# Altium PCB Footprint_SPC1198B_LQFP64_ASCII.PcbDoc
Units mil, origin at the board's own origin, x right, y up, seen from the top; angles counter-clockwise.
Board outline 6000 x 4000 mil, 2 copper layers (Top Layer, Bottom Layer); 1 components, 0 nets, 64 pads, 0 vias.
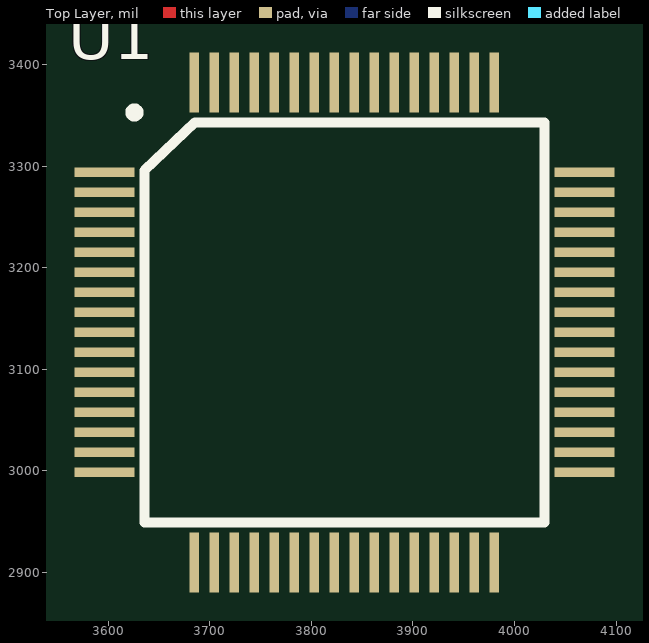
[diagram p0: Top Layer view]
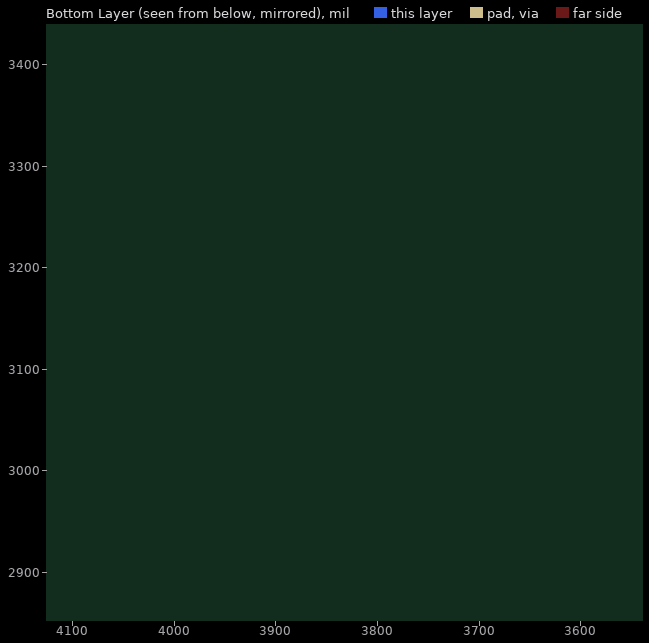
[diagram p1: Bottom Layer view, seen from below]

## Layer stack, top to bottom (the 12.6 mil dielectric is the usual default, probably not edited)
Top Solder: solder mask 0.4, Solder Resist, Dk 3.5
Top Layer: signal copper 1.4
Dielectric 1: dielectric 12.6, FR-4, Dk 4.8
Bottom Layer: signal copper 1.4
Bottom Solder: solder mask 0.4, Solder Resist, Dk 3.5

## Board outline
1000,1000 7000,1000 7000,5000 1000,5000

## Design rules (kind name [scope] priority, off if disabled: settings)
AssemblyTestPointUsage [All] p0: scope1count=1 scope1_0_kind=Board scope1_0_value=Board scope2count=1 scope2_0_kind=Board scope2_0_value=Board commentlength=0
AssemblyTestpoint [All] p0: scope1count=1 scope1_0_kind=Board scope1_0_value=Board scope2count=1 scope2_0_kind=Board scope2_0_value=Board commentlength=0
Clearance [All] p0: scope1count=1 scope1_0_kind=Board scope1_0_value=Board scope2count=1 scope2_0_kind=Board scope2_0_value=Board commentlength=0 gap=10
Clearance [All] p1: gap=10 ignorepadtopadclearanceinfootprint=FALSE except(0: Arc-Hole Track-Hole SMDPad-Hole THPad-Hole Via-Hole Fill-Hole Poly-Hole Region-Hole Text-Hole)
ComponentClearance [All] p0: scope1count=1 scope1_0_kind=Board scope1_0_value=Board scope2count=1 scope2_0_kind=Board scope2_0_value=Board commentlength=0 gap=10 collisioncheckmode=3
DiffPairsRouting [All] p0: scope1count=1 scope1_0_kind=Board scope1_0_value=Board scope2count=1 scope2_0_kind=Board scope2_0_value=Board commentlength=0
FabricationTestPointUsage [All] p0: scope1count=1 scope1_0_kind=Board scope1_0_value=Board scope2count=1 scope2_0_kind=Board scope2_0_value=Board commentlength=0 valid=0 allowmultiple=FALSE
FabricationTestpoint [All] p0: scope1count=1 scope1_0_kind=Board scope1_0_value=Board scope2count=1 scope2_0_kind=Board scope2_0_value=Board commentlength=0 side=3 testpointundercomponent=TRUE minsize=40 maxsize=100 preferedsize=60 minholesize=0 maxholesize=40 preferedholesize=32 testpointgrid=1
FanoutControl Fanout_BGA [All] p0 off: scope1count=1 scope1_0_kind=Board scope1_0_value=Board scope2count=1 scope2_0_kind=Board scope2_0_value=Board commentlength=69 // Protel DXP Scope 1 Expression Was: IsBGA   Fanout_BGA (Default Rule)
FanoutControl Fanout_LCC [All] p0 off: scope1count=1 scope1_0_kind=Board scope1_0_value=Board scope2count=1 scope2_0_kind=Board scope2_0_value=Board commentlength=69 // Protel DXP Scope 1 Expression Was: IsLCC   Fanout_LCC (Default Rule)
FanoutControl Fanout_SOIC [All] p0 off: scope1count=1 scope1_0_kind=Board scope1_0_value=Board scope2count=1 scope2_0_kind=Board scope2_0_value=Board commentlength=71 // Protel DXP Scope 1 Expression Was: IsSOIC   Fanout_SOIC (Default Rule)
FanoutControl Fanout_Small [All] p0 off: scope1count=1 scope1_0_kind=Board scope1_0_value=Board scope2count=1 scope2_0_kind=Board scope2_0_value=Board commentlength=84 // Protel DXP Scope 1 Expression Was: (CompPinCount < 5)   Fanout_Small (Default Rule)
FanoutControl Fanout_Default [All] p0: scope1count=1 scope1_0_kind=Board scope1_0_value=Board scope2count=1 scope2_0_kind=Board scope2_0_value=Board commentlength=30 // Fanout_Default (Default Rule)
Height [All] p0: scope1count=1 scope1_0_kind=Board scope1_0_value=Board scope2count=1 scope2_0_kind=Board scope2_0_value=Board commentlength=0
HoleSize [All] p0: scope1count=1 scope1_0_kind=Board scope1_0_value=Board scope2count=1 scope2_0_kind=Board scope2_0_value=Board commentlength=0 absolutevalues=TRUE maxlimit=100 minlimit=1 maxpercent=80.000 minpercent=20.000
HoleToHoleClearance [All] p0: scope1count=1 scope1_0_kind=Board scope1_0_value=Board scope2count=1 scope2_0_kind=Board scope2_0_value=Board commentlength=0
LayerPairs [All] p0: scope1count=1 scope1_0_kind=Board scope1_0_value=Board scope2count=1 scope2_0_kind=Board scope2_0_value=Board commentlength=0 enforce=TRUE
MinimumSolderMaskSliver [All] p0: scope1count=1 scope1_0_kind=Board scope1_0_value=Board scope2count=1 scope2_0_kind=Board scope2_0_value=Board commentlength=0
NetAntennae [All] p0: scope1count=1 scope1_0_kind=Board scope1_0_value=Board scope2count=1 scope2_0_kind=Board scope2_0_value=Board commentlength=0
PasteMaskExpansion [All] p0: scope1count=1 scope1_0_kind=Board scope1_0_value=Board scope2count=1 scope2_0_kind=Board scope2_0_value=Board commentlength=0 expansion=0
PlaneClearance [All] p0: scope1count=1 scope1_0_kind=Board scope1_0_value=Board scope2count=1 scope2_0_kind=Board scope2_0_value=Board commentlength=0 clearance=20
PlaneConnect [All] p0: scope1count=1 scope1_0_kind=Board scope1_0_value=Board scope2count=1 scope2_0_kind=Board scope2_0_value=Board commentlength=0 planeconnectstyle=Relief reliefexpansion=20 reliefentries=4 reliefconductorwidth=10 reliefairgap=10
PolygonConnect [All] p0: scope1count=1 scope1_0_kind=Board scope1_0_value=Board scope2count=1 scope2_0_kind=Board scope2_0_value=Board commentlength=0 connectstyle=Relief reliefconductorwidth=10 reliefentries=4 polygonreliefangle="90 Angle"
PolygonConnect [All] p1: connectstyle=Relief reliefconductorwidth=10 reliefentries=4 polygonreliefangle="90 Angle" airgapwidth=10
RoutingCorners [All] p0: scope1count=1 scope1_0_kind=Board scope1_0_value=Board scope2count=1 scope2_0_kind=Board scope2_0_value=Board commentlength=0 cornerstyle=45-Degree minsetback=100 maxsetback=100
RoutingLayers [All] p0: scope1count=1 scope1_0_kind=Board scope1_0_value=Board scope2count=1 scope2_0_kind=Board scope2_0_value=Board commentlength=0 top layer=Automatic bottom layer=Automatic
RoutingPriority [All] p0: scope1count=1 scope1_0_kind=Board scope1_0_value=Board scope2count=1 scope2_0_kind=Board scope2_0_value=Board commentlength=0
RoutingTopology [All] p0: scope1count=1 scope1_0_kind=Board scope1_0_value=Board scope2count=1 scope2_0_kind=Board scope2_0_value=Board commentlength=0 topology=Shortest
RoutingVias [All] p0: scope1count=1 scope1_0_kind=Board scope1_0_value=Board scope2count=1 scope2_0_kind=Board scope2_0_value=Board commentlength=0 holewidth=28 width=50 viastyle="Through Hole" minholewidth=28 minwidth=50 maxholewidth=28 maxwidth=50
RoutingVias [All] p1: holewidth=28 width=50 viastyle="Through Hole" minholewidth=28 minwidth=50 maxholewidth=28 maxwidth=50
ShortCircuit [All] p0: scope1count=1 scope1_0_kind=Board scope1_0_value=Board scope2count=1 scope2_0_kind=Board scope2_0_value=Board commentlength=0 allowed=FALSE
SilkToBoardRegionClearance [All] p0: scope1count=1 scope1_0_kind=Board scope1_0_value=Board scope2count=1 scope2_0_kind=Board scope2_0_value=Board commentlength=0
SilkToSilkClearance [All] p0: scope1count=1 scope1_0_kind=Board scope1_0_value=Board scope2count=1 scope2_0_kind=Board scope2_0_value=Board commentlength=0
SilkToSolderMaskClearance [All] p0 off: scope1count=1 scope1_0_kind=Board scope1_0_value=Board scope2count=1 scope2_0_kind=Board scope2_0_value=Board commentlength=44 // Protel DXP Scope 1 Expression Was: IsPad
SolderMaskExpansion [All] p0: scope1count=1 scope1_0_kind=Board scope1_0_value=Board scope2count=1 scope2_0_kind=Board scope2_0_value=Board commentlength=0 expansion=4
SolderMaskExpansion [All] p1: expansion=4 istentingtop=FALSE
UnRoutedNet [All] p0: scope1count=1 scope1_0_kind=Board scope1_0_value=Board scope2count=1 scope2_0_kind=Board scope2_0_value=Board commentlength=0
UnpouredPolygon [All] p0: scope1count=1 scope1_0_kind=Board scope1_0_value=Board scope2count=1 scope2_0_kind=Board scope2_0_value=Board commentlength=0
Width [All] p0: scope1count=1 scope1_0_kind=Board scope1_0_value=Board scope2count=1 scope2_0_kind=Board scope2_0_value=Board commentlength=0 maxlimit=10 minlimit=10 preferedwidth=10
Width [All] p1: maxlimit=10 minlimit=10 preferedwidth=10
30 further rules are at their usual default settings.

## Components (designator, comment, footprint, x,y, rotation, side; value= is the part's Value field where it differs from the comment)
U1 "" LQFP-64_L10.0-W10.0-P0.50-LS12.0-TL 3832.64,3146.22 r0 top

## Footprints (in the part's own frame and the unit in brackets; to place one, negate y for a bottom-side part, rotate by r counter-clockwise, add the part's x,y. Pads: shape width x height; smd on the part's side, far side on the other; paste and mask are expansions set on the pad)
LQFP-64_L10.0-W10.0-P0.50-LS12.0-TL [mm]
  rect 1.5x0.24 smd: 1(-6,3.75) 2(-6,3.25) 3(-6,2.75) 4(-6,2.25) 5(-6,1.75) 6(-6,1.25) 7(-6,0.75) 8(-6,0.25) 9(-6,-0.25) 10(-6,-0.75) 11(-6,-1.25) 12(-6,-1.75) 13(-6,-2.25) 14(-6,-2.75) 15(-6,-3.25) 16(-6,-3.75) 33(6,-3.75) 34(6,-3.25) 35(6,-2.75) 36(6,-2.25) 37(6,-1.75) 38(6,-1.25) 39(6,-0.75) 40(6,-0.25) 41(6,0.25) 42(6,0.75) 43(6,1.25) 44(6,1.75) 45(6,2.25) 46(6,2.75) 47(6,3.25) 48(6,3.75)
  rect 0.24x1.5 smd: 17(-3.75,-6) 18(-3.25,-6) 19(-2.75,-6) 20(-2.25,-6) 21(-1.75,-6) 22(-1.25,-6) 23(-0.75,-6) 24(-0.25,-6) 25(0.25,-6) 26(0.75,-6) 27(1.25,-6) 28(1.75,-6) 29(2.25,-6) 30(2.75,-6) 31(3.25,-6) 32(3.75,-6) 49(3.75,6) 50(3.25,6) 51(2.75,6) 52(2.25,6) 53(1.75,6) 54(1.25,6) 55(0.75,6) 56(0.25,6) 57(-0.25,6) 58(-0.75,6) 59(-1.25,6) 60(-1.75,6) 61(-2.25,6) 62(-2.75,6) 63(-3.25,6) 64(-3.75,6)
  silkscreen extent -5.35,-5 5,5.35

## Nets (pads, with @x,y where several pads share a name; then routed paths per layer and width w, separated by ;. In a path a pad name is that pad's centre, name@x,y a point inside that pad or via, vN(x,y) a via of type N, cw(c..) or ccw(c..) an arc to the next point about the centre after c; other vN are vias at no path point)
pads on no net: U1.1 U1.2 U1.3 U1.4 U1.5 U1.6 U1.7 U1.8 U1.9 U1.10 U1.11 U1.12 U1.13 U1.14 U1.15 U1.16 U1.17 U1.18 U1.19 U1.20 U1.21 U1.22 U1.23 U1.24 U1.25 U1.26 U1.27 U1.28 U1.29 U1.30 U1.31 U1.32 U1.33 U1.34 U1.35 U1.36 U1.37 U1.38 U1.39 U1.40 U1.41 U1.42 U1.43 U1.44 U1.45 U1.46 U1.47 U1.48 U1.49 U1.50 U1.51 U1.52 U1.53 U1.54 U1.55 U1.56 U1.57 U1.58 U1.59 U1.60 U1.61 U1.62 U1.63 U1.64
